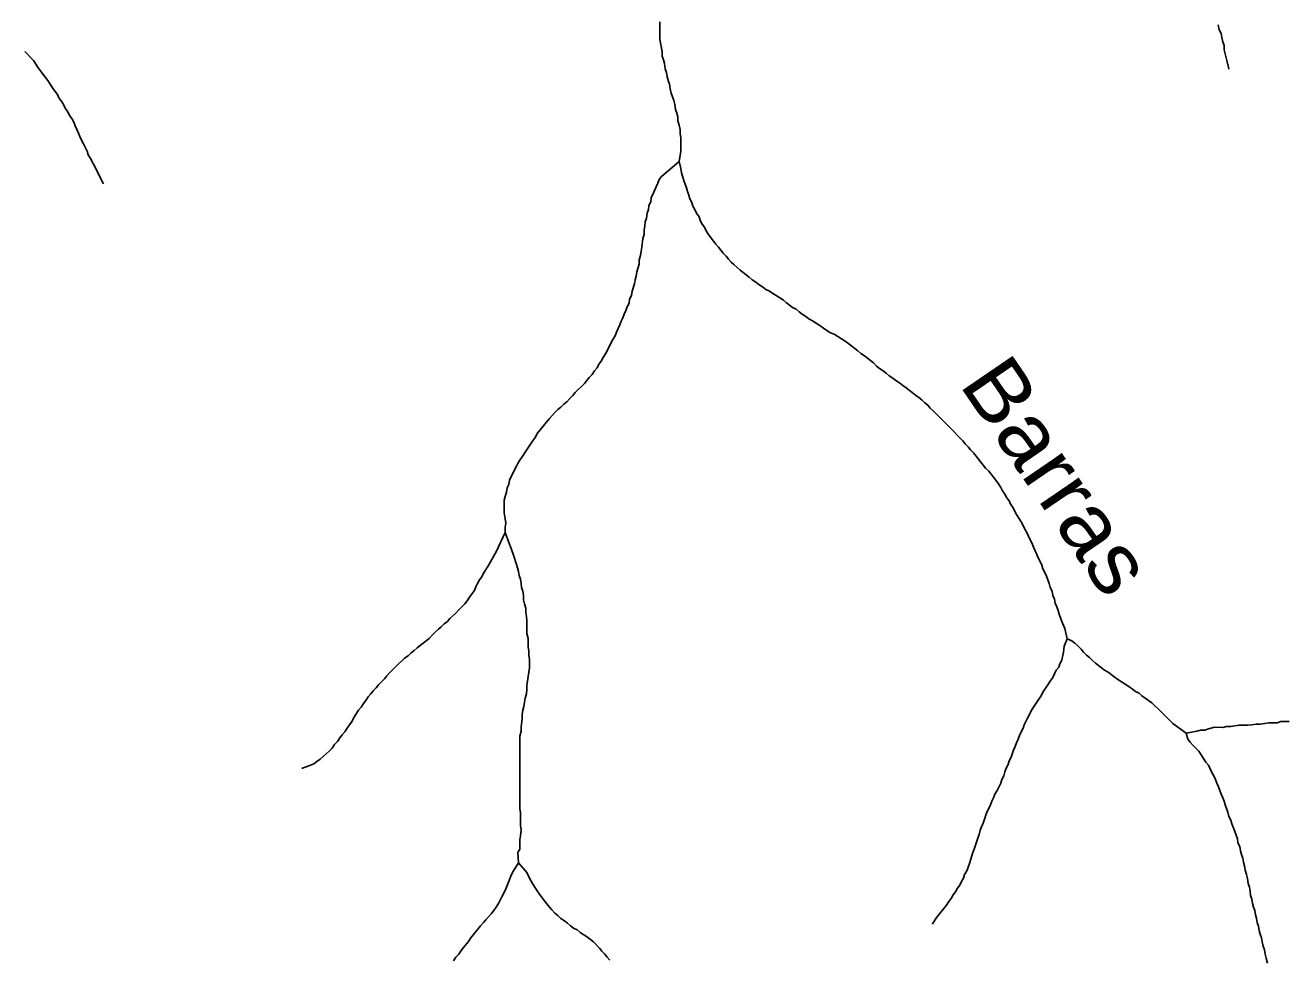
# Model space of a CAD drawing. Extents: x 652.3 to 678, y 7316.9 to 7344.9.
# Drawn here: x 672.84 to 674.503, y 7322.173 to 7323.405 of the extents above; entities that cross this region are included whole.
import ezdxf
from ezdxf.enums import TextEntityAlignment as Align

# ---------------------------------------------------------------- set-up
doc = ezdxf.new("R2010")
doc.units = 0
doc.header["$LTSCALE"] = 0.032
doc.layers.add('61', color=7, linetype='Continuous')
doc.layers.add('7', color=7, linetype='Continuous', lineweight=25)

msp = doc.modelspace()

# ---------------------------------------------------------------- linework, layer by layer
at = {"layer": '7'}
msp.add_line((673.4726, 7322.7359), (673.4606, 7322.7104), dxfattribs=at)
for points in [[(673.6795, 7323.3637), (673.6795, 7323.3692), (673.6787, 7323.3748), (673.6771, 7323.3812), (673.6763, 7323.3867), (673.6763, 7323.3923), (673.6763, 7323.3979), (673.6763, 7323.4035), (673.6763, 7323.409)], [(674.4265, 7323.3468), (674.4264, 7323.3472), (674.4242, 7323.3565), (674.4218, 7323.3669), (674.4202, 7323.3724), (674.4202, 7323.378), (674.4187, 7323.3828), (674.4171, 7323.3883), (674.4163, 7323.3939), (674.4139, 7323.3987), (674.4123, 7323.405)], [(672.8392, 7323.37), (672.8432, 7323.3661), (672.8464, 7323.3621), (672.8504, 7323.3581), (672.8567, 7323.3486), (672.8599, 7323.3446), (672.8631, 7323.3398), (672.8694, 7323.3318), (672.8726, 7323.3271), (672.8758, 7323.3223), (672.879, 7323.3175), (672.8822, 7323.3135), (672.8838, 7323.3088), (672.887, 7323.3048), (672.8901, 7323.3), (672.8925, 7323.2952), (672.8957, 7323.2905), (672.8981, 7323.2857), (672.9013, 7323.2817), (672.9037, 7323.2769), (672.9053, 7323.2722), (672.9076, 7323.2674), (672.91, 7323.2626), (672.9116, 7323.2578), (672.914, 7323.2531), (672.9164, 7323.2483), (672.9212, 7323.2387), (672.9228, 7323.234), (672.9259, 7323.2292), (672.9331, 7323.2149), (672.9355, 7323.2101), (672.9427, 7323.1958), (672.9428, 7323.1954)], [(673.7017, 7323.2252), (673.7041, 7323.2387), (673.7041, 7323.2507), (673.7041, 7323.2563), (673.7033, 7323.2618), (673.7033, 7323.2674), (673.7017, 7323.273), (673.7001, 7323.2785), (673.7001, 7323.2841), (673.6986, 7323.2889), (673.697, 7323.2936), (673.6962, 7323.3), (673.6946, 7323.3056), (673.693, 7323.3104), (673.6914, 7323.3151), (673.6898, 7323.3207), (673.689, 7323.3271), (673.6874, 7323.3318), (673.6858, 7323.3366), (673.685, 7323.3422), (673.6834, 7323.347), (673.6826, 7323.3541), (673.6811, 7323.3589), (673.6795, 7323.3637)], [(673.4726, 7322.7359), (673.4726, 7322.743), (673.4734, 7322.7486), (673.4726, 7322.7542), (673.471, 7322.7621), (673.471, 7322.7788), (673.4726, 7322.7836), (673.4742, 7322.7892), (673.475, 7322.7948), (673.4774, 7322.7995), (673.4781, 7322.8051), (673.4853, 7322.8194), (673.4877, 7322.8242), (673.4901, 7322.829), (673.4965, 7322.8385), (673.4996, 7322.8433), (673.5092, 7322.8576), (673.5124, 7322.8616), (673.5148, 7322.8664), (673.5307, 7322.8863), (673.5346, 7322.8902), (673.5378, 7322.8942), (673.5418, 7322.8982), (673.5458, 7322.9014), (673.5498, 7322.9054), (673.5537, 7322.9085), (673.5577, 7322.9125), (673.5617, 7322.9165), (673.5649, 7322.9205), (673.5768, 7322.9324), (673.58, 7322.9364), (673.5832, 7322.9404), (673.5872, 7322.9443), (673.5903, 7322.9491), (673.5935, 7322.9531), (673.5959, 7322.9579), (673.5991, 7322.9618), (673.6015, 7322.9666), (673.6047, 7322.9714), (673.6094, 7322.9809), (673.6118, 7322.9857), (673.6142, 7322.9905), (673.6174, 7322.9953), (673.619, 7323), (673.6214, 7323.0048), (673.6238, 7323.0096), (673.6254, 7323.0144), (673.6277, 7323.0191), (673.6293, 7323.0239), (673.6317, 7323.0287), (673.6333, 7323.0335), (673.6357, 7323.0382), (673.6365, 7323.0438), (673.6389, 7323.0486), (673.6397, 7323.0541), (673.6429, 7323.0637), (673.6437, 7323.0693), (673.6452, 7323.074), (673.646, 7323.0796), (673.6476, 7323.0852), (673.6492, 7323.09), (673.6492, 7323.0955), (673.6508, 7323.1011), (673.6516, 7323.1067), (673.6524, 7323.1122), (673.654, 7323.1234), (673.6556, 7323.1289), (673.6556, 7323.1345), (673.6564, 7323.1401), (673.6572, 7323.1456), (673.6588, 7323.1504), (673.6596, 7323.1568), (673.6612, 7323.1616), (673.662, 7323.1671), (673.6643, 7323.1719), (673.6651, 7323.1775), (673.6675, 7323.1823), (673.6691, 7323.187), (673.6739, 7323.1966), (673.6755, 7323.2013), (673.6787, 7323.2053), (673.7017, 7323.2252)], [(673.9834, 7322.9396), (673.9786, 7322.9427), (673.9747, 7322.9459), (673.9707, 7322.9491), (673.9659, 7322.9523), (673.9619, 7322.9555), (673.9579, 7322.9595), (673.954, 7322.9626), (673.95, 7322.9658), (673.946, 7322.969), (673.9412, 7322.9722), (673.9373, 7322.9754), (673.9333, 7322.9786), (673.9293, 7322.9817), (673.9253, 7322.9849), (673.9206, 7322.9881), (673.9158, 7322.9913), (673.911, 7322.9945), (673.9062, 7322.9977), (673.9015, 7322.9992), (673.8967, 7323.0024), (673.8919, 7323.0056), (673.8871, 7323.0088), (673.8824, 7323.012), (673.8776, 7323.0152), (673.8728, 7323.0175), (673.8688, 7323.0207), (673.8641, 7323.0239), (673.8601, 7323.0271), (673.8561, 7323.0303), (673.8513, 7323.0327), (673.8473, 7323.0358), (673.8434, 7323.039), (673.8394, 7323.0422), (673.8346, 7323.0454), (673.8298, 7323.0486), (673.8251, 7323.051), (673.8211, 7323.0541), (673.8163, 7323.0565), (673.8115, 7323.0597), (673.8068, 7323.0629), (673.8028, 7323.0661), (673.798, 7323.0693), (673.794, 7323.0724), (673.7901, 7323.0756), (673.7861, 7323.0788), (673.7821, 7323.082), (673.7781, 7323.0852), (673.7741, 7323.0892), (673.7702, 7323.0923), (673.767, 7323.0963), (673.7638, 7323.1003), (673.7598, 7323.1043), (673.7566, 7323.1083), (673.7535, 7323.1122), (673.7503, 7323.1162), (673.7471, 7323.1202), (673.7439, 7323.1242), (673.7407, 7323.1289), (673.7375, 7323.1337), (673.7352, 7323.1385), (673.732, 7323.1425), (673.7296, 7323.1472), (673.728, 7323.152), (673.7248, 7323.1568), (673.7224, 7323.1616), (673.72, 7323.1663), (673.7184, 7323.1711), (673.7161, 7323.1759), (673.7145, 7323.1807), (673.7129, 7323.1854), (673.7113, 7323.1902), (673.7097, 7323.195), (673.7081, 7323.1998), (673.7065, 7323.2045), (673.7049, 7323.2101), (673.7041, 7323.2157), (673.7017, 7323.2252)], [(674.2134, 7322.5958), (674.2102, 7322.6094), (674.2062, 7322.6189), (674.2046, 7322.6237), (674.203, 7322.6285), (674.2014, 7322.6332), (674.1998, 7322.638), (674.1975, 7322.6428), (674.1967, 7322.6483), (674.1943, 7322.6531), (674.1935, 7322.6587), (674.1911, 7322.6635), (674.1895, 7322.669), (674.1879, 7322.6738), (674.1863, 7322.6786), (674.1839, 7322.6834), (674.1815, 7322.6881), (674.1799, 7322.6929), (674.1776, 7322.6977), (674.1752, 7322.7025), (674.1736, 7322.7072), (674.1712, 7322.712), (674.1688, 7322.7168), (674.1672, 7322.7215), (674.1648, 7322.7263), (674.1624, 7322.7311), (674.1601, 7322.7359), (674.1577, 7322.7406), (674.1553, 7322.7454), (674.1529, 7322.7502), (674.1497, 7322.755), (674.1465, 7322.7597), (674.1441, 7322.7645), (674.1418, 7322.7693), (674.1386, 7322.7733), (674.137, 7322.778), (674.1338, 7322.782), (674.1314, 7322.7868), (674.1282, 7322.7908), (674.1258, 7322.7955), (674.1227, 7322.8003), (674.1195, 7322.8051), (674.1163, 7322.8091), (674.1131, 7322.8131), (674.1099, 7322.817), (674.1059, 7322.821), (674.1028, 7322.825), (674.0996, 7322.829), (674.0964, 7322.8329), (674.0932, 7322.8369), (674.09, 7322.8409), (674.0861, 7322.8449), (674.0829, 7322.8489), (674.0789, 7322.8528), (674.0757, 7322.8568), (674.0717, 7322.8608), (674.0678, 7322.8648), (674.0646, 7322.8688), (674.0606, 7322.8727), (674.0566, 7322.8767), (674.0526, 7322.8807), (674.0487, 7322.8847), (674.0447, 7322.8886), (674.0407, 7322.8926), (674.0367, 7322.8966), (674.0327, 7322.8998), (674.0296, 7322.9038), (674.0256, 7322.9069), (674.0216, 7322.9109), (674.0176, 7322.9141), (674.0136, 7322.9173), (674.0089, 7322.9205), (674.0049, 7322.9237), (674.0009, 7322.9268), (673.9969, 7322.93), (673.9922, 7322.9332), (673.9874, 7322.9364), (673.9834, 7322.9396)], [(673.4726, 7322.7359), (673.4774, 7322.7231), (673.4805, 7322.7152), (673.4837, 7322.7048), (673.4869, 7322.6953), (673.4885, 7322.6897), (673.4901, 7322.6849), (673.4909, 7322.6794), (673.4925, 7322.6746), (673.4933, 7322.669), (673.4941, 7322.6635), (673.4957, 7322.6587), (673.4965, 7322.6531), (673.4965, 7322.6475), (673.498, 7322.642), (673.4996, 7322.6364), (673.4996, 7322.6308), (673.5004, 7322.6253), (673.5012, 7322.6197), (673.5012, 7322.603), (673.5028, 7322.5966), (673.5028, 7322.5855), (673.5036, 7322.5799), (673.5036, 7322.5743), (673.5044, 7322.5688), (673.5044, 7322.5576), (673.5036, 7322.5521), (673.5028, 7322.5465), (673.502, 7322.5401), (673.5012, 7322.5346), (673.5012, 7322.529), (673.5004, 7322.5234), (673.4988, 7322.5179), (673.498, 7322.5123), (673.4972, 7322.5067), (673.4957, 7322.5019), (673.4949, 7322.4964), (673.4949, 7322.4908), (673.4933, 7322.4797), (673.4933, 7322.4741), (673.4917, 7322.4677), (673.4917, 7322.3722), (673.4925, 7322.3667), (673.4925, 7322.35), (673.4933, 7322.3444), (673.4925, 7322.3364), (673.4917, 7322.3309), (673.4917, 7322.3189), (673.4893, 7322.3142), (673.4901, 7322.3006)], [(673.4606, 7322.7104), (673.4495, 7322.6913), (673.4439, 7322.6826), (673.4415, 7322.6778), (673.4384, 7322.6738), (673.436, 7322.669), (673.4336, 7322.6643), (673.432, 7322.6595), (673.4288, 7322.6555), (673.4256, 7322.6507), (673.4225, 7322.646), (673.4193, 7322.642), (673.4153, 7322.638), (673.4113, 7322.634), (673.4073, 7322.63), (673.4034, 7322.6261), (673.3994, 7322.6229), (673.3962, 7322.6189), (673.3922, 7322.6157), (673.3882, 7322.6117), (673.3843, 7322.6086), (673.3803, 7322.6046), (673.3763, 7322.6006), (673.3723, 7322.5966), (673.3683, 7322.5934), (673.3644, 7322.5903), (673.3604, 7322.5871), (673.3564, 7322.5839), (673.3524, 7322.5807), (673.3485, 7322.5775), (673.3445, 7322.5735), (673.3397, 7322.5704), (673.3357, 7322.5664), (673.3317, 7322.5632), (673.3278, 7322.5592), (673.3238, 7322.5552), (673.3198, 7322.5513), (673.3166, 7322.5473), (673.3134, 7322.5433), (673.3095, 7322.5393), (673.3055, 7322.5354), (673.3023, 7322.5314), (673.2983, 7322.5274), (673.2951, 7322.5234), (673.292, 7322.5194), (673.2888, 7322.5147), (673.2856, 7322.5107), (673.2824, 7322.5059), (673.2792, 7322.5019), (673.276, 7322.4972), (673.2729, 7322.4924), (673.2705, 7322.4876), (673.2673, 7322.4828), (673.2641, 7322.4781), (673.2609, 7322.4733), (673.2577, 7322.4693), (673.2546, 7322.4653), (673.2514, 7322.4606), (673.2474, 7322.4566), (673.2442, 7322.4518), (673.2402, 7322.4478), (673.2363, 7322.4446), (673.2323, 7322.4407), (673.2283, 7322.4375), (673.2243, 7322.4343), (673.2203, 7322.4311), (673.2156, 7322.4295), (673.21, 7322.4271), (673.2052, 7322.4256), (673.2045, 7322.4253)], [(674.0357, 7322.2199), (674.0359, 7322.2203), (674.0415, 7322.229), (674.0542, 7322.2449), (674.0574, 7322.2497), (674.0606, 7322.2537), (674.063, 7322.2585), (674.0662, 7322.2624), (674.0686, 7322.2672), (674.0717, 7322.2712), (674.0741, 7322.276), (674.0765, 7322.2807), (674.0781, 7322.2855), (674.0813, 7322.2903), (674.0829, 7322.2951), (674.0845, 7322.2998), (674.0892, 7322.3142), (674.0908, 7322.3189), (674.0956, 7322.3333), (674.0972, 7322.338), (674.0988, 7322.3436), (674.1004, 7322.3484), (674.1028, 7322.3531), (674.1075, 7322.3675), (674.1099, 7322.3722), (674.1123, 7322.377), (674.1139, 7322.3818), (674.1163, 7322.3866), (674.1179, 7322.3913), (674.1211, 7322.3961), (674.1258, 7322.4057), (674.1274, 7322.4104), (674.1298, 7322.4152), (674.1314, 7322.4208), (674.133, 7322.4256), (674.1354, 7322.4303), (674.137, 7322.4351), (674.1394, 7322.4399), (674.1425, 7322.4494), (674.1449, 7322.4542), (674.1465, 7322.459), (674.1489, 7322.4637), (674.1505, 7322.4685), (674.1529, 7322.4733), (674.1553, 7322.4781), (674.1569, 7322.4828), (674.1616, 7322.4924), (674.164, 7322.4972), (674.1664, 7322.5019), (674.176, 7322.5163), (674.1792, 7322.521), (674.1815, 7322.5258), (674.1879, 7322.5354), (674.1911, 7322.5401), (674.1943, 7322.5449), (674.199, 7322.5545), (674.2022, 7322.5584), (674.2038, 7322.5632), (674.2062, 7322.568), (674.2086, 7322.5783), (674.2094, 7322.5863), (674.2134, 7322.5958)], [(674.312, 7322.521), (674.3081, 7322.5242), (674.3033, 7322.5266), (674.2993, 7322.5298), (674.2945, 7322.533), (674.2898, 7322.5362), (674.285, 7322.5393), (674.2802, 7322.5425), (674.2754, 7322.5457), (674.2715, 7322.5489), (674.2675, 7322.5521), (674.2627, 7322.5545), (674.2587, 7322.5576), (674.2547, 7322.5608), (674.2508, 7322.564), (674.2468, 7322.5672), (674.2428, 7322.5712), (674.2388, 7322.5743), (674.2348, 7322.5783), (674.2317, 7322.5823), (674.2277, 7322.5863), (674.2237, 7322.5903), (674.2197, 7322.5934), (674.2134, 7322.5958)], [(674.3701, 7322.4717), (674.3526, 7322.4844), (674.3447, 7322.4924), (674.3407, 7322.4964), (674.3367, 7322.5003), (674.3327, 7322.5043), (674.3287, 7322.5083), (674.3248, 7322.5115), (674.3208, 7322.5147), (674.316, 7322.5179), (674.312, 7322.521)], [(674.5062, 7322.4868), (674.495, 7322.4868), (674.4903, 7322.4852), (674.4791, 7322.4852), (674.4736, 7322.4844), (674.468, 7322.4836), (674.4624, 7322.4836), (674.4568, 7322.4828), (674.4513, 7322.482), (674.4401, 7322.482), (674.429, 7322.4805), (674.4234, 7322.4805), (674.4187, 7322.4789), (674.4075, 7322.4797), (674.3996, 7322.4773), (674.3948, 7322.4757), (674.3892, 7322.4757), (674.3844, 7322.4741), (674.3701, 7322.4717)], [(674.4775, 7322.1685), (674.4759, 7322.1749), (674.4744, 7322.1805), (674.4736, 7322.186), (674.472, 7322.1908), (674.4704, 7322.1964), (674.4696, 7322.202), (674.468, 7322.2067), (674.4664, 7322.2115), (674.4656, 7322.2171), (674.464, 7322.2219), (674.4632, 7322.2274), (674.4616, 7322.2322), (674.4608, 7322.2378), (674.4592, 7322.2425), (674.4576, 7322.2473), (674.4568, 7322.2529), (674.4553, 7322.2577), (674.4545, 7322.2632), (674.4537, 7322.2688), (674.4521, 7322.2736), (674.4513, 7322.2799), (674.4497, 7322.2855), (674.4481, 7322.2911), (674.4473, 7322.2967), (674.4457, 7322.3014), (674.4449, 7322.307), (674.4433, 7322.3118), (674.4417, 7322.3165), (674.4409, 7322.3221), (674.4385, 7322.3269), (674.4378, 7322.3325), (674.4362, 7322.3372), (674.4346, 7322.342), (674.4322, 7322.3476), (674.4306, 7322.3523), (674.429, 7322.3571), (674.4266, 7322.3619), (674.425, 7322.3675), (674.4234, 7322.3722), (674.4218, 7322.377), (674.4202, 7322.3818), (674.4187, 7322.3866), (674.4163, 7322.3913), (674.4147, 7322.3961), (674.4131, 7322.4009), (674.4107, 7322.4057), (674.4091, 7322.4104), (674.4067, 7322.4152), (674.4043, 7322.42), (674.4019, 7322.4248), (674.3996, 7322.4295), (674.3964, 7322.4335), (674.3932, 7322.4383), (674.39, 7322.4431), (674.3868, 7322.4478), (674.3828, 7322.4518), (674.3789, 7322.4558), (674.3757, 7322.4598), (674.3725, 7322.4637), (674.3701, 7322.4717)], [(673.4901, 7322.3006), (673.4821, 7322.2879), (673.4797, 7322.2831), (673.4766, 7322.2752), (673.4734, 7322.2664), (673.471, 7322.2616), (673.4686, 7322.2569), (673.4638, 7322.2473), (673.4606, 7322.2425), (673.4575, 7322.2378)], [(673.4901, 7322.3006), (673.5012, 7322.2879), (673.5044, 7322.2807), (673.5084, 7322.2736), (673.5148, 7322.264), (673.5179, 7322.2593), (673.5211, 7322.2545), (673.5275, 7322.2465), (673.5307, 7322.2425), (673.5338, 7322.2386), (673.5378, 7322.2346), (673.5418, 7322.2314), (673.5458, 7322.2274), (673.5506, 7322.2242), (673.5545, 7322.2211), (673.5585, 7322.2179), (673.5625, 7322.2147), (673.5673, 7322.2123), (673.5712, 7322.2091), (673.576, 7322.2059), (673.5808, 7322.2028), (673.5848, 7322.1996), (673.5888, 7322.1964), (673.5967, 7322.1884), (673.5999, 7322.1845), (673.6039, 7322.1805), (673.6071, 7322.1765), (673.6102, 7322.1725)], [(673.4575, 7322.2378), (673.4543, 7322.2338), (673.4511, 7322.2298), (673.4471, 7322.2258), (673.4439, 7322.2219), (673.44, 7322.2179), (673.4272, 7322.202), (673.424, 7322.1972), (673.4177, 7322.1892), (673.4145, 7322.1853), (673.4113, 7322.1805), (673.4073, 7322.1765), (673.4042, 7322.1717)]]:
    msp.add_lwpolyline(points, dxfattribs=at)

# ---------------------------------------------------------------- texts
at = {"layer": '61', "width": 1.1}
msp.add_text('Barras', height=0.08, rotation=304.334, dxfattribs=at).set_placement((674.1677, 7322.7886), align=Align.CENTER)

doc.saveas('drawing.dxf')
